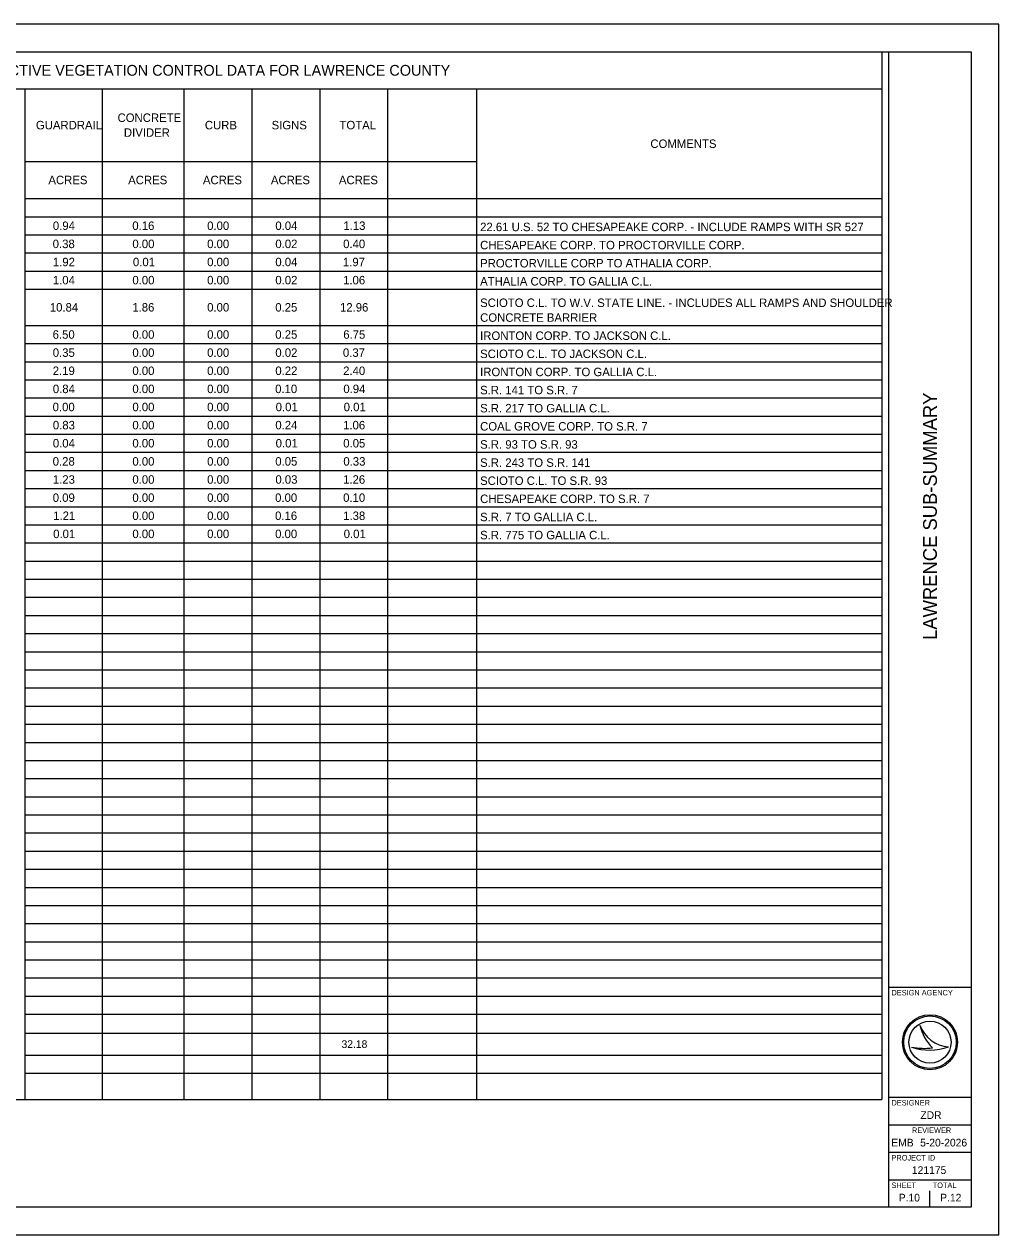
# Model space of a CAD drawing. Extents: x 0 to 34, y 0 to 22.
# Drawn here: x 16.29 to 34, y 0 to 22 of the extents above; entities that cross this region are included whole.
import ezdxf

# ---------------------------------------------------------------- set-up
doc = ezdxf.new("R2010")
doc.units = 0
for name, color, linetype in [('SH_Border', 7, 'Continuous'), ('SH_Cut_Line', 7, 'Continuous'), ('SH_Data', 7, 'Continuous'), ('SH_Text', 7, 'Continuous')]:
    doc.layers.add(name, color=color, linetype=linetype)

msp = doc.modelspace()

# ---------------------------------------------------------------- linework, layer by layer
at = {"layer": 'SH_Border'}
for p, q in [((32, 0.5), (32, 21.5)), ((32, 4.5), (33.5, 4.5)), ((32, 2.5), (33.5, 2.5)), ((32, 2), (33.5, 2)), ((32, 1.5), (33.5, 1.5)), ((32, 1), (33.5, 1))]:
    msp.add_line(p, q, dxfattribs=at)
msp.add_lwpolyline([(1.5, 21.5), (33.5, 21.5), (33.5, 0.5), (1.5, 0.5)], close=True, dxfattribs=at)
at = {"layer": 'SH_Cut_Line'}
msp.add_lwpolyline([(0, 0), (34, 0), (34, 22), (0, 22)], close=True, dxfattribs=at)
at = {"layer": 'SH_Data'}
for p, q in [((32.567, 3.81), (32.567, 3.81)), ((32.417, 3.41), (32.417, 3.41)), ((32.75, 3.5), (32.75, 3.5)), ((33.087, 3.419), (33.087, 3.419)), ((32.375, 0.675), (32.375, 0.675)), ((32.75, 0.5), (32.75, 0.8))]:
    msp.add_line(p, q, dxfattribs=at)
for radius in [0.5, 0.477, 0.477, 0.382]:
    msp.add_circle((32.75, 3.5), radius, dxfattribs=at)
for centre, radius, start, end in [((33.116, 3.998), 0.58, 198.9257, 198.9319), ((33.347, 3.97), 0.796, 191.6379, 191.6421), ((33.116, 3.998), 0.58, 198.9319, 267.1657), ((33.347, 3.97), 0.796, 191.6421, 226.0947), ((32.739, 4.37), 1.013, 251.4576, 290.0832), ((32.648, 4.654), 1.266, 259.4964, 259.4995), ((32.739, 4.37), 1.013, 251.4527, 251.4576), ((32.648, 4.654), 1.266, 259.4995, 276.6672)]:
    msp.add_arc(centre, radius, start, end, dxfattribs=at)
at = {"layer": 'SH_Text'}
for p, q in [((1.5, 21.5), (31.872, 21.5)), ((31.872, 21.5), (31.872, 2.46)), ((7.451, 20.825), (16.302, 20.825)), ((16.28, 20.825), (31.872, 20.825)), ((16.302, 20.825), (16.302, 2.46)), ((17.707, 20.825), (17.707, 2.46)), ((19.189, 20.825), (19.189, 2.46)), ((20.425, 20.825), (20.425, 2.46)), ((21.66, 20.825), (21.66, 2.46)), ((22.895, 20.825), (22.895, 2.46)), ((24.509, 20.825), (24.509, 2.46)), ((16.302, 19.507), (24.509, 19.507)), ((16.302, 18.832), (31.872, 18.832)), ((16.302, 18.502), (31.872, 18.502)), ((16.302, 18.173), (31.872, 18.173)), ((16.302, 17.844), (31.872, 17.844)), ((16.302, 17.514), (31.872, 17.514)), ((16.302, 17.185), (31.872, 17.185)), ((16.302, 16.526), (31.872, 16.526)), ((16.302, 16.196), (31.872, 16.196)), ((16.302, 15.867), (31.872, 15.867)), ((16.302, 15.538), (31.872, 15.538)), ((16.302, 15.208), (31.872, 15.208)), ((16.302, 14.879), (31.872, 14.879)), ((16.302, 14.549), (31.872, 14.549)), ((16.302, 14.22), (31.872, 14.22)), ((16.302, 13.891), (31.872, 13.891)), ((16.302, 13.561), (31.872, 13.561)), ((16.302, 13.232), (31.872, 13.232)), ((16.302, 12.902), (31.872, 12.902)), ((16.302, 12.573), (31.872, 12.573)), ((16.302, 12.244), (31.872, 12.244)), ((16.302, 11.914), (31.872, 11.914)), ((16.302, 11.585), (31.872, 11.585)), ((16.302, 11.255), (31.872, 11.255)), ((16.302, 10.926), (31.872, 10.926)), ((16.302, 10.596), (31.872, 10.596)), ((16.302, 10.267), (31.872, 10.267)), ((16.302, 9.938), (31.872, 9.938)), ((16.302, 9.608), (31.872, 9.608)), ((16.302, 9.279), (31.872, 9.279)), ((16.302, 8.949), (31.872, 8.949)), ((16.302, 8.62), (31.872, 8.62)), ((16.302, 8.291), (31.872, 8.291)), ((16.302, 7.961), (31.872, 7.961)), ((16.302, 7.632), (31.872, 7.632)), ((16.302, 7.302), (31.872, 7.302)), ((16.302, 6.973), (31.872, 6.973)), ((16.302, 6.644), (31.872, 6.644)), ((16.302, 6.314), (31.872, 6.314)), ((16.302, 5.985), (31.872, 5.985)), ((16.302, 5.655), (31.872, 5.655)), ((16.302, 5.326), (31.872, 5.326)), ((16.302, 4.996), (31.872, 4.996)), ((16.302, 4.667), (31.872, 4.667)), ((16.302, 4.338), (31.872, 4.338)), ((16.302, 4.008), (31.872, 4.008)), ((16.302, 3.662), (31.872, 3.662)), ((16.302, 3.267), (31.872, 3.267)), ((16.302, 2.938), (31.872, 2.938)), ((7.451, 2.46), (16.302, 2.46)), ((16.28, 2.46), (31.872, 2.46))]:
    msp.add_line(p, q, dxfattribs=at)

# ---------------------------------------------------------------- texts
at = {"layer": 'SH_Data'}
msp.add_text('LAWRENCE SUB-SUMMARY', height=0.25, rotation=90, dxfattribs=at).set_placement((32.875, 10.811))
for s, height, p in [('DESIGN AGENCY', 0.1, (32.05, 4.35)), ('DESIGNER', 0.1, (32.05, 2.35)), ('ZDR', 0.14, (32.575, 2.105)), ('REVIEWER', 0.1, (32.422, 1.85)), ('EMB', 0.14, (32.047, 1.605)), ('5-20-2026', 0.14, (32.571, 1.605)), ('PROJECT ID', 0.1, (32.05, 1.35)), ('121175', 0.14, (32.421, 1.105)), ('SHEET', 0.1, (32.05, 0.85)), ('TOTAL', 0.1, (32.8, 0.85)), ('P.10', 0.14, (32.182, 0.605)), ('P.12', 0.14, (32.935, 0.605))]:
    msp.add_text(s, height=height, dxfattribs=at).set_placement(p)
at = {"layer": 'SH_Text'}
for s, height, p in [('HERBICIDAL SPRAYING NONSELECTIVE VEGETATION CONTROL DATA FOR LAWRENCE COUNTY', 0.196, (11.683, 21.064)), ('GUARDRAIL', 0.154, (16.503, 20.089)), ('CONCRETE', 0.154, (17.987, 20.224)), ('CURB', 0.154, (19.573, 20.089)), ('SIGNS', 0.154, (20.786, 20.089)), ('TOTAL', 0.154, (22.02, 20.089)), ('DIVIDER', 0.154, (18.102, 19.954)), ('COMMENTS', 0.154, (27.669, 19.751)), ('ACRES', 0.154, (16.73, 19.092)), ('ACRES', 0.154, (18.18, 19.092)), ('ACRES', 0.154, (19.538, 19.092)), ('ACRES', 0.154, (20.774, 19.092)), ('ACRES', 0.154, (22.009, 19.092)), ('0.94', 0.154, (16.811, 18.261)), ('0.16', 0.154, (18.255, 18.261)), ('0.00', 0.154, (19.615, 18.261)), ('0.04', 0.154, (20.854, 18.261)), ('1.13', 0.154, (22.09, 18.261)), ('22.61 U.S. 52 TO CHESAPEAKE CORP. - INCLUDE RAMPS WITH SR 527', 0.154, (24.575, 18.239)), ('0.38', 0.154, (16.808, 17.931)), ('0.00', 0.154, (18.256, 17.931)), ('0.00', 0.154, (19.615, 17.931)), ('0.02', 0.154, (20.854, 17.931)), ('0.40', 0.154, (22.086, 17.931)), ('CHESAPEAKE CORP. TO PROCTORVILLE CORP.', 0.154, (24.575, 17.909)), ('1.92', 0.154, (16.811, 17.602)), ('0.01', 0.154, (18.266, 17.602)), ('0.00', 0.154, (19.615, 17.602)), ('0.04', 0.154, (20.854, 17.602)), ('1.97', 0.154, (22.082, 17.602)), ('PROCTORVILLE CORP TO ATHALIA CORP.', 0.154, (24.575, 17.58)), ('1.04', 0.154, (16.811, 17.272)), ('0.00', 0.154, (18.256, 17.272)), ('0.00', 0.154, (19.615, 17.272)), ('0.02', 0.154, (20.854, 17.272)), ('1.06', 0.154, (22.085, 17.272)), ('ATHALIA CORP. TO GALLIA C.L.', 0.154, (24.575, 17.251)), ('SCIOTO C.L. TO W.V. STATE LINE. - INCLUDES ALL RAMPS AND SHOULDER ', 0.154, (24.575, 16.861)), ('10.84', 0.154, (16.756, 16.778)), ('1.86', 0.154, (18.255, 16.778)), ('0.00', 0.154, (19.615, 16.778)), ('0.25', 0.154, (20.853, 16.778)), ('12.96', 0.154, (22.029, 16.778)), ('CONCRETE BARRIER', 0.154, (24.575, 16.592)), ('6.50', 0.154, (16.807, 16.284)), ('0.00', 0.154, (18.256, 16.284)), ('0.00', 0.154, (19.615, 16.284)), ('0.25', 0.154, (20.853, 16.284)), ('6.75', 0.154, (22.088, 16.284)), ('IRONTON CORP. TO JACKSON C.L.', 0.154, (24.575, 16.262)), ('0.35', 0.154, (16.809, 15.955)), ('0.00', 0.154, (18.256, 15.955)), ('0.00', 0.154, (19.615, 15.955)), ('0.02', 0.154, (20.854, 15.955)), ('0.37', 0.154, (22.082, 15.955)), ('SCIOTO C.L. TO JACKSON C.L.', 0.154, (24.575, 15.933)), ('2.19', 0.154, (16.809, 15.625)), ('0.00', 0.154, (18.256, 15.625)), ('0.00', 0.154, (19.615, 15.625)), ('0.22', 0.154, (20.854, 15.625)), ('2.40', 0.154, (22.086, 15.625)), ('IRONTON CORP. TO GALLIA C.L.', 0.154, (24.575, 15.604)), ('0.84', 0.154, (16.811, 15.296)), ('0.00', 0.154, (18.256, 15.296)), ('0.00', 0.154, (19.615, 15.296)), ('0.10', 0.154, (20.85, 15.296)), ('0.94', 0.154, (22.09, 15.296)), ('S.R. 141 TO S.R. 7', 0.154, (24.575, 15.274)), ('0.00', 0.154, (16.807, 14.967)), ('0.00', 0.154, (18.256, 14.967)), ('0.00', 0.154, (19.615, 14.967)), ('0.01', 0.154, (20.86, 14.967)), ('0.01', 0.154, (22.096, 14.967)), ('S.R. 217 TO GALLIA C.L.', 0.154, (24.575, 14.945)), ('0.83', 0.154, (16.811, 14.637)), ('0.00', 0.154, (18.256, 14.637)), ('0.00', 0.154, (19.615, 14.637)), ('0.24', 0.154, (20.854, 14.637)), ('1.06', 0.154, (22.085, 14.637)), ('COAL GROVE CORP. TO S.R. 7', 0.154, (24.575, 14.615)), ('0.04', 0.154, (16.811, 14.308)), ('0.00', 0.154, (18.256, 14.308)), ('0.00', 0.154, (19.615, 14.308)), ('0.01', 0.154, (20.86, 14.308)), ('0.05', 0.154, (22.088, 14.308)), ('S.R. 93 TO S.R. 93', 0.154, (24.575, 14.286)), ('0.28', 0.154, (16.808, 13.978)), ('0.00', 0.154, (18.256, 13.978)), ('0.00', 0.154, (19.615, 13.978)), ('0.05', 0.154, (20.853, 13.978)), ('0.33', 0.154, (22.09, 13.978)), ('S.R. 243 TO S.R. 141', 0.154, (24.575, 13.956)), ('1.23', 0.154, (16.811, 13.649)), ('0.00', 0.154, (18.256, 13.649)), ('0.00', 0.154, (19.615, 13.649)), ('0.03', 0.154, (20.855, 13.649)), ('1.26', 0.154, (22.085, 13.649)), ('SCIOTO C.L. TO S.R. 93', 0.154, (24.575, 13.627)), ('0.09', 0.154, (16.809, 13.319)), ('0.00', 0.154, (18.256, 13.319)), ('0.00', 0.154, (19.615, 13.319)), ('0.00', 0.154, (20.85, 13.319)), ('0.10', 0.154, (22.086, 13.319)), ('CHESAPEAKE CORP. TO S.R. 7', 0.154, (24.575, 13.298)), ('1.21', 0.154, (16.817, 12.99)), ('0.00', 0.154, (18.256, 12.99)), ('0.00', 0.154, (19.615, 12.99)), ('0.16', 0.154, (20.849, 12.99)), ('1.38', 0.154, (22.087, 12.99)), ('S.R. 7 TO GALLIA C.L.', 0.154, (24.575, 12.968)), ('0.01', 0.154, (16.817, 12.661)), ('0.00', 0.154, (18.256, 12.661)), ('0.00', 0.154, (19.615, 12.661)), ('0.00', 0.154, (20.85, 12.661)), ('0.01', 0.154, (22.096, 12.661)), ('S.R. 775 TO GALLIA C.L.', 0.154, (24.575, 12.639)), ('32.18', 0.14, (22.057, 3.395))]:
    msp.add_text(s, height=height, dxfattribs=at).set_placement(p)

doc.saveas('drawing.dxf')
